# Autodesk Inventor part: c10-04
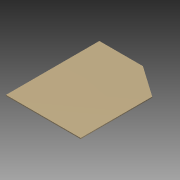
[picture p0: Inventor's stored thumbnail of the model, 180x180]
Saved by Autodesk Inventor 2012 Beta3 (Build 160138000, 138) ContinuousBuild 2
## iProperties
Created: 2011-01
Part Number: c10-04
Material: Aluminum-6061
Document SubType Name: Sheet Metal
Designer: Beta-8540w
Density: 2.71 g/cm^3
Sheet Metal Rule: Aluminum 3 mm
Author: Beta-8540w
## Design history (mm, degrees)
node "Face1"
  sketch "Sketch1"
    geometry: L1 (0, 0)-(240, 0); L2 (240, 0)-(240, 300); L3 (240, 300)-(0, 300); L4 (0, 300)-(0, 0); L5 (140, 300)-(240, 229.979)
    constraints: 10 end point, 2 parallel, 2 point on line, 1 horizontal, 1 perpendicular
    dimensions: "d0" = 240 distance of L3.end L2.end; "d1" = 300 distance of L2.end L1.end; "d2" = 35 deg angle of L3 L5; "d3" = 100 distance from line of L2 L5.start
body "Solid1"
face "Plate1" dims "Thickness" = 3 (derived)
other parameters: "BendRadius" = 2 (derived), "BendReliefWidth" = 3 (= Thickness), "BendReliefDepth" = 1.5 (= 0.5 x Thickness), "CornerReliefSize" = 12 (= 4 x Thickness), "SeamGap" = 0.01, "MinimumRemnant" = 6 (= 2 x Thickness), "TransitionRadius" = 2 (= BendRadius), "JacobiRadiusSize" = 2 (= BendRadius), "GapSize" = 1.5 (= 0.5 x Thickness), "d4" = 2 (= BendRadius)
